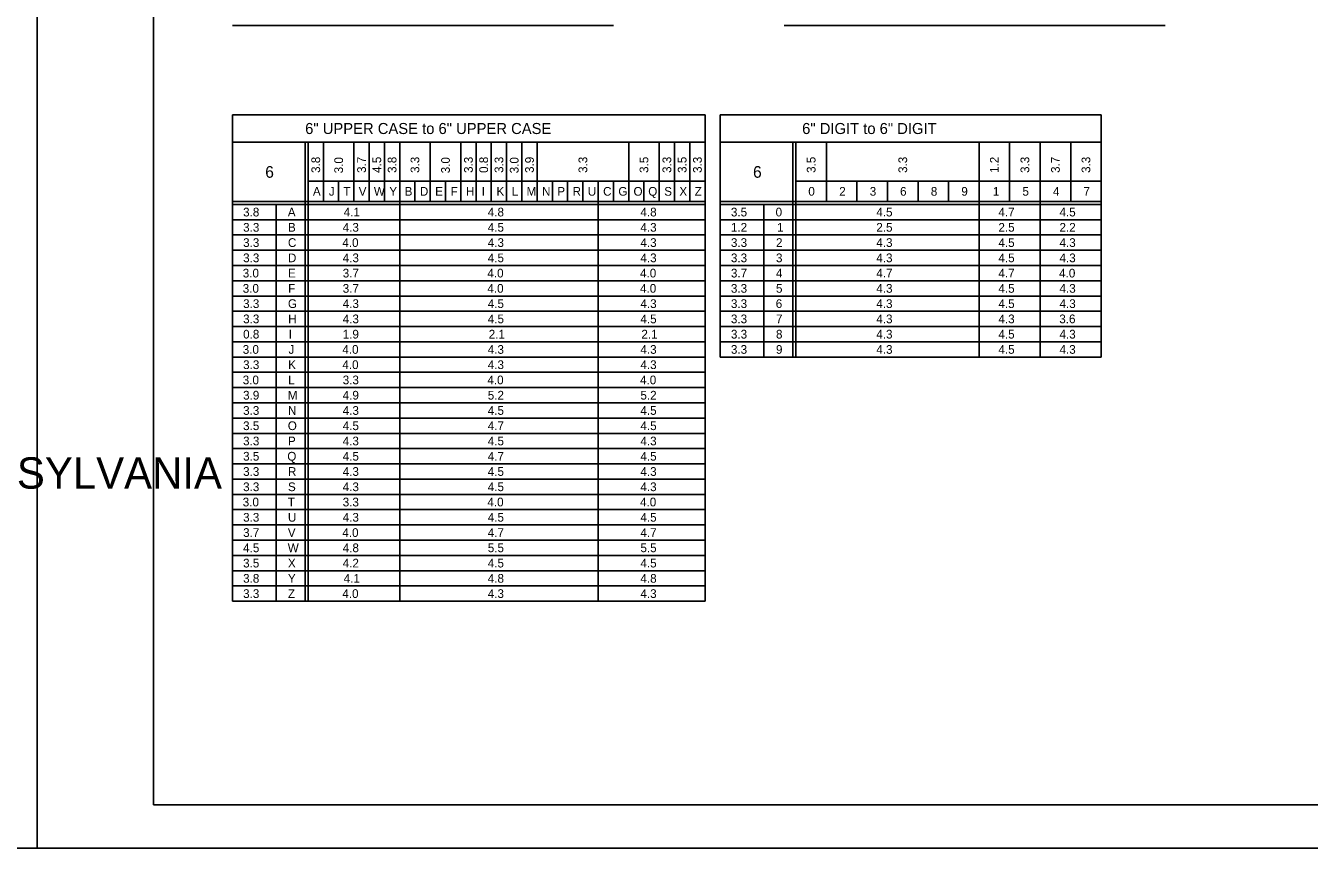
# Model space of a CAD drawing. Extents: x 637580 to 641849, y 297270 to 299646.
# Drawn here: x 640099.4 to 640540.8, y 297269.6 to 297552.6 of the extents above; entities that cross this region are included whole.
import ezdxf

# ---------------------------------------------------------------- set-up
doc = ezdxf.new("R2010")
doc.units = 0
for name, color, linetype in [('1', 7, 'Continuous'), ('2', 7, 'Continuous'), ('XCS-GRID-HVGL', 7, 'Continuous')]:
    doc.layers.add(name, color=color, linetype=linetype)

msp = doc.modelspace()

# ---------------------------------------------------------------- linework, layer by layer
at = {"layer": '1'}
for p, q in [((640143.31, 297848.63), (640143.31, 297284.63)), ((640929.31, 297284.63), (640143.31, 297284.63)), ((640143.31, 297284.63), (640729.31, 297284.63))]:
    msp.add_line(p, q, dxfattribs=at)
at = {"layer": '2'}
for p, q in [((640170.51, 297552.63), (640301.51, 297552.63)), ((640360.21, 297552.63), (640491.21, 297552.63)), ((640333.01, 297522), (640170.51, 297522)), ((640170.51, 297522), (640170.51, 297354.63)), ((640333.01, 297522), (640333.01, 297354.63)), ((640469.26, 297522), (640338.26, 297522)), ((640338.26, 297522), (640338.26, 297438.63)), ((640469.26, 297438.63), (640469.26, 297522)), ((640170.51, 297512.5), (640333.01, 297512.5)), ((640195.51, 297512.5), (640195.51, 297354.63)), ((640196.51, 297512.5), (640196.51, 297354.63)), ((640201.76, 297512.5), (640201.76, 297492.13)), ((640212.26, 297512.5), (640212.26, 297492.13)), ((640217.51, 297512.5), (640217.51, 297492.13)), ((640222.76, 297512.5), (640222.76, 297492.13)), ((640228.01, 297512.5), (640228.01, 297354.63)), ((640238.51, 297512.5), (640238.51, 297492.13)), ((640249.01, 297512.5), (640249.01, 297492.13)), ((640254.26, 297512.5), (640254.26, 297492.13)), ((640259.51, 297512.5), (640259.51, 297492.13)), ((640264.76, 297512.5), (640264.76, 297492.13)), ((640270.01, 297512.5), (640270.01, 297492.13)), ((640275.26, 297512.5), (640275.26, 297492.13)), ((640306.76, 297512.5), (640306.76, 297492.13)), ((640317.26, 297512.5), (640317.26, 297492.13)), ((640322.51, 297512.5), (640322.51, 297492.13)), ((640327.76, 297512.5), (640327.76, 297492.13)), ((640338.26, 297512.5), (640469.26, 297512.5)), ((640363.26, 297512.5), (640363.26, 297438.63)), ((640364.26, 297512.5), (640364.26, 297438.63)), ((640374.76, 297512.5), (640374.76, 297492.13)), ((640427.26, 297512.5), (640427.26, 297438.63)), ((640437.76, 297512.5), (640437.76, 297492.13)), ((640448.26, 297512.5), (640448.26, 297438.63)), ((640458.76, 297512.5), (640458.76, 297492.13)), ((640196.51, 297499.13), (640333.01, 297499.13)), ((640207.01, 297499.13), (640207.01, 297492.13)), ((640233.26, 297499.13), (640233.26, 297492.13)), ((640243.76, 297499.13), (640243.76, 297492.13)), ((640280.51, 297499.13), (640280.51, 297492.13)), ((640285.76, 297499.13), (640285.76, 297492.13)), ((640291.01, 297499.13), (640291.01, 297492.13)), ((640291.01, 297499.13), (640291.01, 297492.13)), ((640296.26, 297499.13), (640296.26, 297354.63)), ((640301.51, 297499.13), (640301.51, 297492.13)), ((640312.01, 297499.13), (640312.01, 297492.13)), ((640364.26, 297499.13), (640469.26, 297499.13)), ((640385.26, 297499.13), (640385.26, 297492.13)), ((640395.76, 297499.13), (640395.76, 297492.13)), ((640406.26, 297499.13), (640406.26, 297492.13)), ((640416.76, 297499.13), (640416.76, 297492.13)), ((640333.01, 297492.13), (640170.51, 297492.13)), ((640333.01, 297491.13), (640170.51, 297491.13)), ((640185.51, 297491.13), (640185.51, 297354.63)), ((640469.26, 297492.13), (640338.26, 297492.13)), ((640469.26, 297491.13), (640338.26, 297491.13)), ((640353.26, 297491.13), (640353.26, 297438.63)), ((640333.01, 297485.88), (640170.51, 297485.88)), ((640469.26, 297485.88), (640338.26, 297485.88)), ((640333.01, 297480.63), (640170.51, 297480.63)), ((640469.26, 297480.63), (640338.26, 297480.63)), ((640333.01, 297475.38), (640170.51, 297475.38)), ((640469.26, 297475.38), (640338.26, 297475.38)), ((640333.01, 297470.13), (640170.51, 297470.13)), ((640469.26, 297470.13), (640338.26, 297470.13)), ((640333.01, 297464.88), (640170.51, 297464.88)), ((640469.26, 297464.88), (640338.26, 297464.88)), ((640333.01, 297459.63), (640170.51, 297459.63)), ((640469.26, 297459.63), (640338.26, 297459.63)), ((640333.01, 297454.38), (640170.51, 297454.38)), ((640469.26, 297454.38), (640338.26, 297454.38)), ((640333.01, 297449.13), (640170.51, 297449.13)), ((640469.26, 297449.13), (640338.26, 297449.13)), ((640333.01, 297443.88), (640170.51, 297443.88)), ((640469.26, 297443.88), (640338.26, 297443.88)), ((640333.01, 297438.63), (640170.51, 297438.63)), ((640338.26, 297438.63), (640469.26, 297438.63)), ((640333.01, 297433.38), (640170.51, 297433.38)), ((640333.01, 297428.13), (640170.51, 297428.13)), ((640333.01, 297422.88), (640170.51, 297422.88)), ((640333.01, 297417.63), (640170.51, 297417.63)), ((640333.01, 297412.38), (640170.51, 297412.38)), ((640333.01, 297407.13), (640170.51, 297407.13)), ((640333.01, 297401.88), (640170.51, 297401.88)), ((640333.01, 297396.63), (640170.51, 297396.63)), ((640333.01, 297391.38), (640170.51, 297391.38)), ((640333.01, 297386.13), (640170.51, 297386.13)), ((640333.01, 297380.88), (640170.51, 297380.88)), ((640333.01, 297375.63), (640170.51, 297375.63)), ((640333.01, 297370.38), (640170.51, 297370.38)), ((640333.01, 297365.13), (640170.51, 297365.13)), ((640333.01, 297359.88), (640170.51, 297359.88)), ((640170.51, 297354.63), (640170.51, 297354.63)), ((640170.51, 297354.63), (640333.01, 297354.63))]:
    msp.add_line(p, q, dxfattribs=at)
at = {"layer": 'XCS-GRID-HVGL'}
for points in [[(639262.31, 297863.63), (640103.31, 297863.63), (640103.31, 297269.63), (639262.31, 297269.63)], [(640103.31, 297863.63), (640944.31, 297863.63), (640944.31, 297269.63), (640103.31, 297269.63)]]:
    msp.add_lwpolyline(points, close=True, dxfattribs=at)

# ---------------------------------------------------------------- texts
at = {"layer": '1'}
msp.add_text('COMMONWEALTH OF PENNSYLVANIA', height=10.7828, dxfattribs=at).set_placement((639900.9, 297393.36))
at = {"layer": '2'}
for s, height, p in [('6" UPPER CASE to 6" UPPER CASE', 3.8, (640195.5, 297515.35)), ('6" DIGIT to 6" DIGIT', 3.8, (640366.41, 297515.35)), ('6', 4, (640181.77, 297500.31)), ('6', 4, (640349.52, 297500.31)), ('A', 3, (640198.16, 297494.13)), ('J', 3, (640203.64, 297494.13)), ('T', 3, (640208.64, 297494.13)), ('V', 3, (640213.91, 297494.13)), ('W', 3, (640219.13, 297494.13)), ('Y', 3, (640224.44, 297494.13)), ('B', 3, (640229.7, 297494.13)), ('D', 3, (640234.95, 297494.13)), ('E', 3, (640240.22, 297494.13)), ('F', 3, (640245.52, 297494.13)), ('H', 3, (640250.79, 297494.13)), ('I', 3, (640256.2, 297494.13)), ('K', 3, (640261.29, 297494.13)), ('L', 3, (640266.54, 297494.13)), ('M', 3, (640271.63, 297494.13)), ('N', 3, (640276.95, 297494.13)), ('P', 3, (640282.2, 297494.13)), ('R', 3, (640287.45, 297494.13)), ('U', 3, (640292.69, 297494.13)), ('C', 3, (640297.95, 297494.13)), ('G', 3, (640303.2, 297494.13)), ('O', 3, (640308.41, 297494.13)), ('Q', 3, (640313.48, 297494.13)), ('S', 3, (640318.97, 297494.13)), ('X', 3, (640324.19, 297494.13)), ('Z', 3, (640329.45, 297494.13)), ('0', 3, (640368.53, 297494.13)), ('2', 3, (640379.16, 297494.13)), ('3', 3, (640389.66, 297494.13)), ('6', 3, (640400.08, 297494.13)), ('8', 3, (640410.66, 297494.13)), ('9', 3, (640421.15, 297494.13)), ('1', 3, (640432, 297494.13)), ('5', 3, (640442.16, 297494.13)), ('4', 3, (640452.66, 297494.13)), ('7', 3, (640463.16, 297494.13)), ('3.8', 3, (640174.16, 297487)), ('A', 3, (640189.53, 297487)), ('4.1', 3, (640208.75, 297487)), ('4.8', 3, (640258.29, 297487)), ('4.8', 3, (640310.79, 297487)), ('3.5', 3, (640341.91, 297487)), ('0', 3, (640357.28, 297487)), ('4.5', 3, (640391.91, 297487)), ('4.7', 3, (640433.91, 297487)), ('4.5', 3, (640454.91, 297487)), ('3.3', 3, (640174.16, 297481.75)), ('B', 3, (640189.58, 297481.75)), ('4.3', 3, (640208.41, 297481.75)), ('4.5', 3, (640258.29, 297481.75)), ('4.3', 3, (640310.79, 297481.75)), ('1.2', 3, (640341.91, 297481.75)), ('1', 3, (640357.75, 297481.75)), ('2.5', 3, (640391.91, 297481.75)), ('2.5', 3, (640433.91, 297481.75)), ('2.2', 3, (640454.91, 297481.75)), ('3.3', 3, (640174.16, 297476.5)), ('C', 3, (640189.58, 297476.5)), ('4.0', 3, (640208.28, 297476.5)), ('4.3', 3, (640258.29, 297476.5)), ('4.3', 3, (640310.79, 297476.5)), ('3.3', 3, (640341.91, 297476.5)), ('2', 3, (640357.41, 297476.5)), ('4.3', 3, (640391.91, 297476.5)), ('4.5', 3, (640433.91, 297476.5)), ('4.3', 3, (640454.91, 297476.5)), ('3.3', 3, (640174.16, 297471.25)), ('D', 3, (640189.58, 297471.25)), ('4.3', 3, (640208.41, 297471.25)), ('4.5', 3, (640258.29, 297471.25)), ('4.3', 3, (640310.79, 297471.25)), ('3.3', 3, (640341.91, 297471.25)), ('3', 3, (640357.41, 297471.25)), ('4.3', 3, (640391.91, 297471.25)), ('4.5', 3, (640433.91, 297471.25)), ('4.3', 3, (640454.91, 297471.25)), ('3.0', 3, (640174.03, 297466)), ('E', 3, (640189.59, 297466)), ('3.7', 3, (640208.41, 297466)), ('4.0', 3, (640258.16, 297466)), ('4.0', 3, (640310.66, 297466)), ('3.7', 3, (640341.91, 297466)), ('4', 3, (640357.41, 297466)), ('4.7', 3, (640391.91, 297466)), ('4.7', 3, (640433.91, 297466)), ('4.0', 3, (640454.78, 297466)), ('3.0', 3, (640174.03, 297460.75)), ('F', 3, (640189.65, 297460.75)), ('3.7', 3, (640208.41, 297460.75)), ('4.0', 3, (640258.16, 297460.75)), ('4.0', 3, (640310.66, 297460.75)), ('3.3', 3, (640341.91, 297460.75)), ('5', 3, (640357.41, 297460.75)), ('4.3', 3, (640391.91, 297460.75)), ('4.5', 3, (640433.91, 297460.75)), ('4.3', 3, (640454.91, 297460.75)), ('3.3', 3, (640174.16, 297455.5)), ('G', 3, (640189.58, 297455.5)), ('4.3', 3, (640208.41, 297455.5)), ('4.5', 3, (640258.29, 297455.5)), ('4.3', 3, (640310.79, 297455.5)), ('3.3', 3, (640341.91, 297455.5)), ('6', 3, (640357.33, 297455.5)), ('4.3', 3, (640391.91, 297455.5)), ('4.5', 3, (640433.91, 297455.5)), ('4.3', 3, (640454.91, 297455.5)), ('3.3', 3, (640174.16, 297450.25)), ('H', 3, (640189.66, 297450.25)), ('4.3', 3, (640208.41, 297450.25)), ('4.5', 3, (640258.29, 297450.25)), ('4.5', 3, (640310.79, 297450.25)), ('3.3', 3, (640341.91, 297450.25)), ('7', 3, (640357.41, 297450.25)), ('4.3', 3, (640391.91, 297450.25)), ('4.3', 3, (640433.91, 297450.25)), ('3.6', 3, (640454.83, 297450.25)), ('0.8', 3, (640174.16, 297445)), ('I', 3, (640189.83, 297445)), ('1.9', 3, (640208.4, 297445)), ('2.1', 3, (640258.63, 297445)), ('2.1', 3, (640311.13, 297445)), ('3.3', 3, (640341.91, 297445)), ('8', 3, (640357.41, 297445)), ('4.3', 3, (640391.91, 297445)), ('4.5', 3, (640433.91, 297445)), ('4.3', 3, (640454.91, 297445)), ('3.0', 3, (640174.03, 297439.75)), ('J', 3, (640189.77, 297439.75)), ('4.0', 3, (640208.28, 297439.75)), ('4.3', 3, (640258.29, 297439.75)), ('4.3', 3, (640310.79, 297439.75)), ('3.3', 3, (640341.91, 297439.75)), ('9', 3, (640357.4, 297439.75)), ('4.3', 3, (640391.91, 297439.75)), ('4.5', 3, (640433.91, 297439.75)), ('4.3', 3, (640454.91, 297439.75)), ('3.3', 3, (640174.16, 297434.5)), ('K', 3, (640189.66, 297434.5)), ('4.0', 3, (640208.28, 297434.5)), ('4.3', 3, (640258.29, 297434.5)), ('4.3', 3, (640310.79, 297434.5)), ('3.0', 3, (640174.03, 297429.25)), ('L', 3, (640189.66, 297429.25)), ('3.3', 3, (640208.41, 297429.25)), ('4.0', 3, (640258.16, 297429.25)), ('4.0', 3, (640310.66, 297429.25)), ('3.9', 3, (640174.15, 297424)), ('M', 3, (640189.51, 297424)), ('4.9', 3, (640208.4, 297424)), ('5.2', 3, (640258.29, 297424)), ('5.2', 3, (640310.79, 297424)), ('3.3', 3, (640174.16, 297418.75)), ('N', 3, (640189.58, 297418.75)), ('4.3', 3, (640208.41, 297418.75)), ('4.5', 3, (640258.29, 297418.75)), ('4.5', 3, (640310.79, 297418.75)), ('3.5', 3, (640174.16, 297413.5)), ('O', 3, (640189.53, 297413.5)), ('4.5', 3, (640208.41, 297413.5)), ('4.7', 3, (640258.29, 297413.5)), ('4.5', 3, (640310.79, 297413.5)), ('3.3', 3, (640174.16, 297408.25)), ('P', 3, (640189.58, 297408.25)), ('4.3', 3, (640208.41, 297408.25)), ('4.5', 3, (640258.29, 297408.25)), ('4.3', 3, (640310.79, 297408.25)), ('3.5', 3, (640174.16, 297403)), ('Q', 3, (640189.35, 297403)), ('4.5', 3, (640208.41, 297403)), ('4.7', 3, (640258.29, 297403)), ('4.5', 3, (640310.79, 297403)), ('3.3', 3, (640174.16, 297397.75)), ('R', 3, (640189.58, 297397.75)), ('4.3', 3, (640208.41, 297397.75)), ('4.5', 3, (640258.29, 297397.75)), ('4.3', 3, (640310.79, 297397.75)), ('3.3', 3, (640174.16, 297392.5)), ('S', 3, (640189.59, 297392.5)), ('4.3', 3, (640208.41, 297392.5)), ('4.5', 3, (640258.29, 297392.5)), ('4.3', 3, (640310.79, 297392.5)), ('3.0', 3, (640174.03, 297387.25)), ('T', 3, (640189.52, 297387.25)), ('3.3', 3, (640208.41, 297387.25)), ('4.0', 3, (640258.16, 297387.25)), ('4.0', 3, (640310.66, 297387.25)), ('3.3', 3, (640174.16, 297382)), ('U', 3, (640189.57, 297382)), ('4.3', 3, (640208.41, 297382)), ('4.5', 3, (640258.29, 297382)), ('4.5', 3, (640310.79, 297382)), ('3.7', 3, (640174.16, 297376.75)), ('V', 3, (640189.53, 297376.75)), ('4.0', 3, (640208.28, 297376.75)), ('4.7', 3, (640258.29, 297376.75)), ('4.7', 3, (640310.79, 297376.75)), ('4.5', 3, (640174.16, 297371.5)), ('W', 3, (640189.51, 297371.5)), ('4.8', 3, (640208.41, 297371.5)), ('5.5', 3, (640258.29, 297371.5)), ('5.5', 3, (640310.79, 297371.5)), ('3.5', 3, (640174.16, 297366.25)), ('X', 3, (640189.57, 297366.25)), ('4.2', 3, (640208.41, 297366.25)), ('4.5', 3, (640258.29, 297366.25)), ('4.5', 3, (640310.79, 297366.25)), ('3.8', 3, (640174.16, 297361)), ('Y', 3, (640189.57, 297361)), ('4.1', 3, (640208.75, 297361)), ('4.8', 3, (640258.29, 297361)), ('4.8', 3, (640310.79, 297361)), ('3.3', 3, (640174.16, 297355.75)), ('Z', 3, (640189.58, 297355.75)), ('4.0', 3, (640208.28, 297355.75)), ('4.3', 3, (640258.29, 297355.75)), ('4.3', 3, (640310.79, 297355.75))]:
    msp.add_text(s, height=height, dxfattribs=at).set_placement(p)
for s, p in [('3.8', (640200.64, 297501.96)), ('3.0', (640208.51, 297501.83)), ('3.7', (640216.39, 297501.96)), ('4.5', (640221.64, 297501.96)), ('3.8', (640226.89, 297501.96)), ('3.3', (640234.76, 297501.96)), ('3.0', (640245.26, 297501.83)), ('3.3', (640253.14, 297501.96)), ('0.8', (640258.39, 297501.96)), ('3.3', (640263.64, 297501.96)), ('3.0', (640268.89, 297501.83)), ('3.9', (640274.14, 297501.95)), ('3.3', (640292.51, 297501.96)), ('3.5', (640313.51, 297501.96)), ('3.3', (640321.39, 297501.96)), ('3.5', (640326.64, 297501.96)), ('3.3', (640331.89, 297501.96)), ('3.5', (640371.01, 297501.96)), ('3.3', (640402.51, 297501.96)), ('1.2', (640434.01, 297501.96)), ('3.3', (640444.51, 297501.96)), ('3.7', (640455.01, 297501.96)), ('3.3', (640465.51, 297501.96))]:
    msp.add_text(s, height=3, rotation=90, dxfattribs=at).set_placement(p)

doc.saveas('drawing.dxf')
